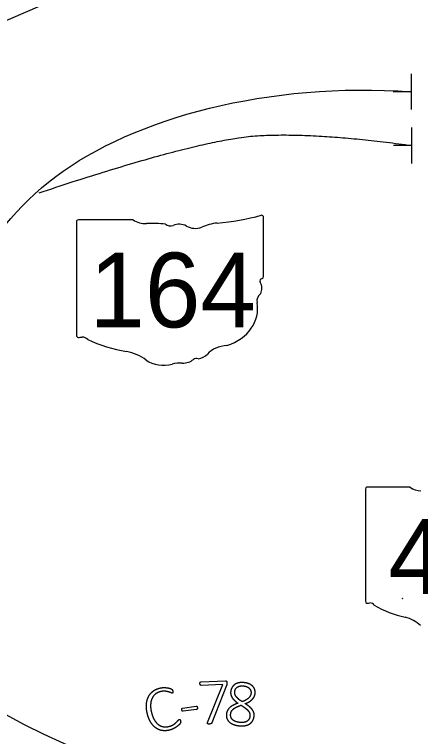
# Model space of a CAD drawing. Extents: x -202 to 1556, y 0 to 676.
# Drawn here: x 150.7 to 191.4, y 37.1 to 109.6 of the extents above; entities that cross this region are included whole.
import ezdxf

# ---------------------------------------------------------------- set-up
doc = ezdxf.new("R2010")
doc.units = 0
for name, color, linetype in [('Default', 7, 'Continuous'), ('GM_X_City_Street', 7, 'Continuous'), ('GM_X_Major_River_Text', 7, 'Continuous'), ('GM_X_Minor_Lake', 7, 'Continuous'), ('GM_X_State_Location', 7, 'Continuous'), ('SH_Data', 7, 'Continuous')]:
    doc.layers.add(name, color=color, linetype=linetype)

msp = doc.modelspace()

# ---------------------------------------------------------------- linework, layer by layer
at = {"layer": 'Default'}
msp.add_open_spline([(153.155, 91.676), (169.005, 96.963), (180.564, 97.806), (190.501, 96.425)], degree=2, dxfattribs=at)
at = {"layer": 'GM_X_City_Street'}
for p, q in [((175.663, 83.279), (175.663, 89.234)), ((156.914, 88.756), (156.914, 77.372)), ((162.589, 88.952), (157.098, 88.952)), ((175.662, 83.28), (175.663, 83.279)), ((185.889, 61.951), (185.889, 50.694)), ((190.378, 62.145), (186.035, 62.145))]:
    msp.add_line(p, q, dxfattribs=at)
for centre, radius, start, end in [((186.059, 61.975), 0.172, 98.1301, 188.1301), ((191.413, 63.451), 1.667, 231.61951, 271.11188), ((186.06, 50.67), 0.173, 171.95839, 258.30661), ((186.087, 51.821), 1.323, 267.33899, 280.60386), ((186.357, 50.045), 0.477, 29.74838, 93.27175), ((192.379, 60.159), 11.358, 240.41292, 257.1985), ((188.993, 45.637), 3.554, 47.18416, 75.83597)]:
    msp.add_arc(centre, radius, start, end, dxfattribs=at)
for centre, major_axis, start_param, end_param in [((168.985, 104.473), (19.884, 0), 4.814394, 5.042369), ((175.456, 89.259), (0.209, 0), 6.141152, 7.989035), ((157.129, 88.78), (0.217, 0), 1.712693, 3.28349), ((163.897, 90.274), (2.107, 0), 4.042523, 4.731795), ((164.596, 82.561), (7.564, 0), 1.404758, 1.657858), ((166.313, 88.839), (0.608, 0), 3.836095, 5.185415), ((167.205, 87.524), (1.264, 0), 0.950623, 2.079405), ((171.521, 85.475), (4, 0), 1.699011, 2.107814), ((168.836, 89.328), (1.52, 0), 4.081561, 5.145723), ((175.615, 82.842), (0.323, 0), 1.883978, 3.671073), ((173.56, 82.089), (1.939, 0), 5.934695, 6.695948), ((175.441, 83.256), (0.223, 0), 5.05454, 6.418171), ((176.411, 80.787), (1.411, 0), 2.387724, 3.262537), ((170.098, 80.029), (4.973, 0), 5.101752, 6.440018), ((157.131, 77.347), (0.219, 0), 3.00124, 4.508301), ((157.164, 78.511), (1.672, 0), 4.665946, 4.897461), ((157.506, 76.715), (0.603, 0), 0.519207, 1.627899), ((165.119, 86.943), (14.359, 0), 4.195997, 4.488961), ((172.195, 74.175), (2.724, 0), 1.647645, 2.488434), ((160.838, 72.257), (4.493, 0), 0.823519, 1.323587), ((168.744, 76.268), (1.607, 0), 4.937069, 5.64225), ((165.697, 76.658), (2.851, 0), 4.026481, 4.996735), ((167.553, 75.806), (1.519, 0), 4.691044, 5.507374), ((168.927, 74.703), (0.428, 0), 1.147584, 2.315152), ((167.344, 72.722), (2.342, 0), 1.495662, 1.94098)]:
    msp.add_ellipse(centre, major_axis=major_axis, ratio=0.8, start_param=start_param, end_param=end_param, dxfattribs=at)
at = {"layer": 'GM_X_Major_River_Text'}
for p, q in [((189.583, 50.986), (189.575, 50.972)), ((189.589, 50.971), (189.589, 50.971)), ((189.595, 50.977), (189.597, 50.977)), ((189.597, 50.975), (189.595, 50.975)), ((189.6, 50.976), (189.6, 50.976)), ((189.605, 50.971), (189.605, 50.971))]:
    msp.add_line(p, q, dxfattribs=at)
for points in [[(189.575, 50.97), (189.584, 50.97), (189.584, 50.965)], [(189.589, 50.972), (189.586, 50.972), (189.586, 50.986)], [(189.586, 50.965), (189.586, 50.97), (189.589, 50.97)]]:
    msp.add_lwpolyline(points, dxfattribs=at)
msp.add_lwpolyline([(189.584, 50.984), (189.584, 50.972), (189.576, 50.972), (189.584, 50.984)], close=True, dxfattribs=at)
for points in [[(189.575, 50.972), (189.574, 50.972), (189.574, 50.972)], [(189.574, 50.972), (189.574, 50.972), (189.574, 50.971)], [(189.574, 50.971), (189.574, 50.971), (189.574, 50.971)], [(189.574, 50.971), (189.574, 50.971), (189.574, 50.971)], [(189.574, 50.971), (189.574, 50.971), (189.574, 50.97)], [(189.574, 50.97), (189.574, 50.97), (189.574, 50.97)], [(189.574, 50.97), (189.574, 50.97), (189.575, 50.97)], [(189.575, 50.97), (189.575, 50.97), (189.575, 50.97)], [(189.584, 50.986), (189.583, 50.986), (189.583, 50.986)], [(189.583, 50.986), (189.583, 50.986), (189.583, 50.986)], [(189.583, 50.986), (189.583, 50.986), (189.583, 50.986)], [(189.585, 50.986), (189.585, 50.986), (189.584, 50.986)], [(189.584, 50.986), (189.584, 50.986), (189.584, 50.986)], [(189.584, 50.965), (189.584, 50.965), (189.584, 50.965)], [(189.584, 50.965), (189.584, 50.965), (189.584, 50.965)], [(189.584, 50.965), (189.584, 50.965), (189.584, 50.965)], [(189.584, 50.965), (189.585, 50.965), (189.585, 50.965)], [(189.586, 50.986), (189.586, 50.986), (189.585, 50.986)], [(189.585, 50.986), (189.585, 50.986), (189.585, 50.986)], [(189.585, 50.965), (189.585, 50.965), (189.585, 50.965)], [(189.585, 50.965), (189.586, 50.965), (189.586, 50.965)], [(189.586, 50.986), (189.586, 50.986), (189.586, 50.986)], [(189.586, 50.965), (189.586, 50.965), (189.586, 50.965)], [(189.586, 50.965), (189.586, 50.965), (189.586, 50.965)], [(189.589, 50.971), (189.589, 50.972), (189.589, 50.972)], [(189.589, 50.971), (189.589, 50.971), (189.589, 50.971)], [(189.589, 50.97), (189.589, 50.97), (189.589, 50.971)], [(189.589, 50.97), (189.589, 50.97), (189.589, 50.97)], [(189.592, 50.967), (189.592, 50.968), (189.592, 50.968)], [(189.592, 50.968), (189.592, 50.968), (189.593, 50.968)], [(189.592, 50.966), (189.592, 50.967), (189.592, 50.967)], [(189.592, 50.967), (189.592, 50.967), (189.592, 50.967)], [(189.593, 50.966), (189.593, 50.966), (189.592, 50.966)], [(189.592, 50.966), (189.592, 50.966), (189.592, 50.966)], [(189.592, 50.966), (189.592, 50.966), (189.592, 50.966)], [(189.593, 50.984), (189.593, 50.984), (189.593, 50.985)], [(189.593, 50.985), (189.593, 50.985), (189.594, 50.985)], [(189.593, 50.983), (189.593, 50.983), (189.593, 50.984)], [(189.593, 50.984), (189.593, 50.984), (189.593, 50.984)], [(189.593, 50.984), (189.593, 50.984), (189.593, 50.984)], [(189.593, 50.984), (189.593, 50.984), (189.593, 50.984)], [(189.594, 50.983), (189.593, 50.983), (189.593, 50.983)], [(189.593, 50.983), (189.593, 50.983), (189.593, 50.983)], [(189.593, 50.983), (189.593, 50.983), (189.593, 50.983)], [(189.593, 50.983), (189.593, 50.983), (189.593, 50.983)], [(189.593, 50.968), (189.593, 50.968), (189.593, 50.968)], [(189.593, 50.968), (189.594, 50.968), (189.594, 50.967)], [(189.594, 50.965), (189.594, 50.965), (189.593, 50.966)], [(189.594, 50.985), (189.594, 50.985), (189.595, 50.986)], [(189.595, 50.984), (189.594, 50.983), (189.594, 50.983)], [(189.594, 50.975), (189.594, 50.975), (189.594, 50.976)], [(189.594, 50.976), (189.594, 50.976), (189.594, 50.976)], [(189.594, 50.976), (189.594, 50.976), (189.595, 50.976)], [(189.595, 50.975), (189.594, 50.975), (189.594, 50.975)], [(189.594, 50.967), (189.595, 50.967), (189.596, 50.967)], [(189.596, 50.965), (189.595, 50.965), (189.594, 50.965)], [(189.595, 50.986), (189.596, 50.986), (189.596, 50.986)], [(189.596, 50.984), (189.595, 50.984), (189.595, 50.984)], [(189.595, 50.976), (189.595, 50.976), (189.595, 50.977)], [(189.595, 50.977), (189.595, 50.977), (189.595, 50.977)], [(189.595, 50.975), (189.595, 50.975), (189.595, 50.975)], [(189.595, 50.975), (189.595, 50.975), (189.595, 50.975)], [(189.596, 50.986), (189.597, 50.986), (189.598, 50.986)], [(189.598, 50.985), (189.597, 50.985), (189.596, 50.984)], [(189.596, 50.967), (189.597, 50.966), (189.598, 50.966)], [(189.598, 50.965), (189.597, 50.965), (189.596, 50.965)], [(189.597, 50.977), (189.598, 50.977), (189.599, 50.977)], [(189.599, 50.975), (189.598, 50.975), (189.597, 50.975)], [(189.598, 50.986), (189.6, 50.986), (189.601, 50.986)], [(189.6, 50.984), (189.599, 50.985), (189.598, 50.985)], [(189.598, 50.966), (189.599, 50.966), (189.6, 50.967)], [(189.601, 50.965), (189.6, 50.965), (189.598, 50.965)], [(189.599, 50.977), (189.6, 50.977), (189.6, 50.978)], [(189.601, 50.974), (189.601, 50.974), (189.599, 50.975)], [(189.601, 50.984), (189.6, 50.984), (189.6, 50.984)], [(189.6, 50.978), (189.601, 50.978), (189.602, 50.979)], [(189.602, 50.977), (189.601, 50.976), (189.6, 50.976)], [(189.6, 50.976), (189.601, 50.976), (189.602, 50.975)], [(189.6, 50.967), (189.601, 50.967), (189.602, 50.967)], [(189.601, 50.986), (189.602, 50.986), (189.603, 50.985)], [(189.602, 50.982), (189.601, 50.983), (189.601, 50.984)], [(189.602, 50.972), (189.602, 50.973), (189.601, 50.974)], [(189.603, 50.966), (189.602, 50.965), (189.601, 50.965)], [(189.602, 50.981), (189.602, 50.982), (189.602, 50.982)], [(189.602, 50.979), (189.602, 50.98), (189.602, 50.981)], [(189.603, 50.978), (189.602, 50.977), (189.602, 50.977)], [(189.602, 50.975), (189.603, 50.975), (189.603, 50.974)], [(189.603, 50.971), (189.603, 50.971), (189.602, 50.972)], [(189.602, 50.969), (189.603, 50.97), (189.603, 50.971)], [(189.602, 50.967), (189.602, 50.968), (189.602, 50.969)], [(189.603, 50.985), (189.603, 50.984), (189.604, 50.983)], [(189.604, 50.979), (189.603, 50.978), (189.603, 50.978)], [(189.603, 50.974), (189.604, 50.974), (189.605, 50.973)], [(189.604, 50.968), (189.604, 50.967), (189.603, 50.966)], [(189.604, 50.983), (189.604, 50.982), (189.604, 50.981)], [(189.604, 50.981), (189.604, 50.98), (189.604, 50.979)], [(189.605, 50.971), (189.605, 50.969), (189.604, 50.968)], [(189.605, 50.973), (189.605, 50.972), (189.605, 50.971)]]:
    msp.add_open_spline(points, degree=2, dxfattribs=at)
at = {"layer": 'GM_X_Minor_Lake'}
for p, q in [((190.455, 103.624), (190.478, 100.024)), ((190.467, 101.824), (188.667, 101.813)), ((190.49, 98.224), (190.513, 94.625)), ((190.501, 96.425), (188.702, 96.413))]:
    msp.add_line(p, q, dxfattribs=at)
at = {"layer": 'GM_X_State_Location'}
for p, q in [((169.4, 42.603), (171.841, 42.69)), ((171.95, 42.232), (170.483, 38.502)), ((171.998, 42.519), (171.998, 42.519)), ((174.406, 41.437), (174.406, 41.437)), ((167.548, 39.973), (168.91, 40.159)), ((169.027, 40.01), (169.027, 40.01)), ((168.955, 39.834), (167.593, 39.648)), ((174.298, 39.138), (174.298, 39.138)), ((174.722, 39.148), (174.722, 39.148)), ((167.339, 38.676), (167.339, 38.676))]:
    msp.add_line(p, q, dxfattribs=at)
msp.add_lwpolyline([(170.056, 38.509), (171.585, 42.324), (169.413, 42.246)], dxfattribs=at)
for points in [[(169.286, 42.421), (169.284, 42.464), (169.291, 42.497)], [(169.321, 42.295), (169.288, 42.346), (169.286, 42.421)], [(169.291, 42.497), (169.298, 42.53), (169.314, 42.554)], [(169.314, 42.554), (169.329, 42.577), (169.35, 42.589)], [(169.413, 42.246), (169.354, 42.243), (169.321, 42.295)], [(169.35, 42.589), (169.371, 42.602), (169.4, 42.603)], [(171.841, 42.69), (171.884, 42.692), (171.914, 42.683)], [(171.914, 42.683), (171.943, 42.674), (171.961, 42.652)], [(171.975, 42.306), (171.965, 42.272), (171.95, 42.232)], [(171.961, 42.652), (171.978, 42.63), (171.987, 42.597)], [(171.99, 42.376), (171.985, 42.341), (171.975, 42.306)], [(171.987, 42.597), (171.997, 42.565), (171.998, 42.519)], [(171.998, 42.445), (171.996, 42.411), (171.99, 42.376)], [(171.998, 42.519), (172, 42.48), (171.998, 42.445)], [(172.757, 42.32), (172.587, 42.196), (172.491, 42.019)], [(173.173, 42.499), (172.926, 42.444), (172.757, 42.32)], [(172.783, 41.618), (172.819, 41.927), (173.047, 42.08)], [(173.047, 42.08), (173.274, 42.233), (173.669, 42.188)], [(173.744, 42.518), (173.421, 42.555), (173.173, 42.499)], [(173.669, 42.188), (173.862, 42.166), (174.008, 42.103)], [(174.261, 42.38), (174.047, 42.483), (173.744, 42.518)], [(174.008, 42.103), (174.155, 42.04), (174.249, 41.941)], [(174.607, 42.131), (174.475, 42.278), (174.261, 42.38)], [(174.79, 41.803), (174.739, 41.984), (174.607, 42.131)], [(164.105, 41.071), (164.265, 41.407), (164.549, 41.637)], [(164.794, 41.357), (164.582, 41.18), (164.466, 40.911)], [(164.549, 41.637), (164.834, 41.867), (165.225, 41.966)], [(165.295, 41.608), (165.006, 41.535), (164.794, 41.357)], [(165.225, 41.966), (165.409, 42.013), (165.591, 42.022)], [(165.766, 41.658), (165.559, 41.675), (165.295, 41.608)], [(165.591, 42.022), (165.773, 42.031), (165.933, 42.014)], [(166.125, 41.596), (165.973, 41.642), (165.766, 41.658)], [(165.933, 42.014), (166.093, 41.997), (166.227, 41.957)], [(166.375, 41.506), (166.277, 41.55), (166.125, 41.596)], [(166.227, 41.957), (166.36, 41.916), (166.414, 41.884)], [(166.517, 41.473), (166.472, 41.461), (166.375, 41.506)], [(166.414, 41.884), (166.468, 41.852), (166.484, 41.836)], [(166.484, 41.836), (166.5, 41.82), (166.512, 41.798)], [(166.512, 41.798), (166.524, 41.775), (166.535, 41.746)], [(166.552, 41.495), (166.539, 41.478), (166.517, 41.473)], [(166.535, 41.746), (166.546, 41.717), (166.556, 41.679)], [(166.57, 41.538), (166.564, 41.512), (166.552, 41.495)], [(166.556, 41.679), (166.567, 41.634), (166.571, 41.6)], [(166.571, 41.6), (166.575, 41.565), (166.57, 41.538)], [(172.371, 41.637), (172.351, 41.464), (172.389, 41.306)], [(172.491, 42.019), (172.394, 41.842), (172.371, 41.637)], [(172.804, 41.352), (172.767, 41.478), (172.783, 41.618)], [(172.931, 41.105), (172.841, 41.226), (172.804, 41.352)], [(174.406, 41.437), (174.374, 41.161), (174.145, 40.955)], [(174.249, 41.941), (174.344, 41.843), (174.383, 41.715)], [(174.383, 41.715), (174.423, 41.587), (174.406, 41.437)], [(174.723, 41.106), (174.8, 41.257), (174.82, 41.433)], [(174.82, 41.433), (174.842, 41.622), (174.79, 41.803)], [(163.92, 40.303), (163.945, 40.734), (164.105, 41.071)], [(164.466, 40.911), (164.351, 40.641), (164.338, 40.286)], [(172.389, 41.306), (172.427, 41.149), (172.52, 41.002)], [(172.52, 41.002), (172.614, 40.856), (172.762, 40.721)], [(172.762, 40.721), (172.91, 40.585), (173.109, 40.456)], [(173.167, 40.863), (173.021, 40.984), (172.931, 41.105)], [(173.52, 40.61), (173.314, 40.743), (173.167, 40.863)], [(174.145, 40.955), (173.916, 40.749), (173.52, 40.61)], [(173.821, 40.41), (174.042, 40.494), (174.217, 40.597)], [(174.217, 40.597), (174.392, 40.701), (174.519, 40.828)], [(174.519, 40.828), (174.646, 40.955), (174.723, 41.106)], [(164.021, 39.369), (163.894, 39.872), (163.92, 40.303)], [(164.338, 40.286), (164.325, 39.931), (164.434, 39.502)], [(167.473, 39.797), (167.46, 39.888), (167.483, 39.927)], [(167.483, 39.927), (167.506, 39.967), (167.548, 39.973)], [(168.91, 40.159), (168.93, 40.162), (168.949, 40.156)], [(168.949, 40.156), (168.968, 40.15), (168.983, 40.133)], [(169.018, 39.878), (168.997, 39.84), (168.955, 39.834)], [(168.983, 40.133), (168.999, 40.115), (169.01, 40.085)], [(169.01, 40.085), (169.021, 40.055), (169.027, 40.01)], [(169.027, 40.01), (169.04, 39.915), (169.018, 39.878)], [(172.3, 40.041), (172.152, 39.913), (172.06, 39.75)], [(172.654, 40.269), (172.449, 40.169), (172.3, 40.041)], [(172.458, 39.661), (172.53, 39.784), (172.658, 39.888)], [(173.109, 40.456), (172.858, 40.37), (172.654, 40.269)], [(172.658, 39.888), (172.785, 39.992), (172.974, 40.081)], [(172.974, 40.081), (173.162, 40.17), (173.41, 40.256)], [(173.41, 40.256), (173.647, 40.107), (173.823, 39.976)], [(174.237, 40.116), (174.058, 40.261), (173.821, 40.41)], [(173.823, 39.976), (174, 39.845), (174.112, 39.715)], [(174.532, 39.818), (174.417, 39.972), (174.237, 40.116)], [(164.362, 38.529), (164.146, 38.88), (164.021, 39.369)], [(164.434, 39.502), (164.538, 39.092), (164.707, 38.797)], [(167.518, 39.674), (167.485, 39.706), (167.473, 39.797)], [(167.593, 39.648), (167.55, 39.642), (167.518, 39.674)], [(171.945, 39.379), (171.916, 39.132), (171.991, 38.93)], [(172.06, 39.75), (171.969, 39.588), (171.945, 39.379)], [(172.551, 38.807), (172.328, 39.029), (172.368, 39.378)], [(172.368, 39.378), (172.386, 39.537), (172.458, 39.661)], [(174.298, 39.138), (174.259, 38.807), (173.994, 38.641)], [(174.112, 39.715), (174.224, 39.585), (174.27, 39.445)], [(174.27, 39.445), (174.317, 39.304), (174.298, 39.138)], [(174.695, 39.501), (174.646, 39.665), (174.532, 39.818)], [(174.571, 38.685), (174.691, 38.881), (174.722, 39.148)], [(174.722, 39.148), (174.743, 39.337), (174.695, 39.501)], [(164.865, 37.973), (164.578, 38.177), (164.362, 38.529)], [(164.707, 38.797), (164.877, 38.502), (165.101, 38.327)], [(166.626, 38.308), (166.802, 38.422), (166.918, 38.536)], [(166.918, 38.536), (167.035, 38.65), (167.105, 38.737)], [(167.105, 38.737), (167.176, 38.824), (167.224, 38.837)], [(167.32, 38.453), (167.297, 38.415), (167.213, 38.321)], [(167.224, 38.837), (167.243, 38.841), (167.258, 38.837)], [(167.258, 38.837), (167.272, 38.832), (167.286, 38.813)], [(167.286, 38.813), (167.299, 38.795), (167.312, 38.761)], [(167.312, 38.761), (167.326, 38.727), (167.339, 38.676)], [(167.348, 38.513), (167.342, 38.491), (167.32, 38.453)], [(167.339, 38.676), (167.348, 38.641), (167.352, 38.612)], [(167.355, 38.559), (167.355, 38.535), (167.348, 38.513)], [(167.352, 38.612), (167.356, 38.582), (167.355, 38.559)], [(170.05, 38.401), (170.033, 38.42), (170.037, 38.446)], [(170.037, 38.446), (170.041, 38.473), (170.056, 38.509)], [(170.449, 38.436), (170.43, 38.411), (170.401, 38.397)], [(170.483, 38.502), (170.468, 38.462), (170.449, 38.436)], [(171.991, 38.93), (172.065, 38.728), (172.227, 38.578)], [(172.227, 38.578), (172.39, 38.427), (172.633, 38.331)], [(173.26, 38.53), (172.775, 38.586), (172.551, 38.807)], [(173.994, 38.641), (173.729, 38.475), (173.26, 38.53)], [(174.254, 38.369), (174.451, 38.489), (174.571, 38.685)], [(165.501, 37.713), (165.152, 37.768), (164.865, 37.973)], [(165.101, 38.327), (165.324, 38.152), (165.601, 38.1)], [(166.237, 37.756), (165.849, 37.658), (165.501, 37.713)], [(165.601, 38.1), (165.878, 38.049), (166.193, 38.129)], [(166.193, 38.129), (166.45, 38.194), (166.626, 38.308)], [(166.666, 37.916), (166.478, 37.817), (166.237, 37.756)], [(166.991, 38.121), (166.854, 38.015), (166.666, 37.916)], [(167.213, 38.321), (167.129, 38.227), (166.991, 38.121)], [(170.108, 38.373), (170.067, 38.382), (170.05, 38.401)], [(170.225, 38.368), (170.15, 38.365), (170.108, 38.373)], [(170.33, 38.376), (170.287, 38.37), (170.225, 38.368)], [(170.401, 38.397), (170.372, 38.383), (170.33, 38.376)], [(172.633, 38.331), (172.876, 38.235), (173.186, 38.2)], [(173.186, 38.2), (173.518, 38.161), (173.787, 38.205)], [(173.787, 38.205), (174.056, 38.248), (174.254, 38.369)]]:
    msp.add_open_spline(points, degree=2, dxfattribs=at)
at = {"layer": 'SH_Data'}
msp.add_circle((192.681, 118.45), 90, dxfattribs=at)
for points in [[(72.676, 92.438), (98.675, 92.219), (111.174, 94.546), (130.998, 99.432), (168.349, 118.148), (182.667, 118.561)], [(99.584, 38.494), (114.011, 45.821), (142.225, 70.89), (149.271, 95.631), (176.178, 102.836), (190.467, 101.824)]]:
    msp.add_open_spline(points, degree=3, dxfattribs=at)

# ---------------------------------------------------------------- texts
at = {"layer": 'GM_X_City_Street'}
for s, p in [('164', (158.183, 78.174)), ('43', (188.189, 51.428))]:
    msp.add_text(s, height=7.5, dxfattribs=at).set_placement(p)

doc.saveas('drawing.dxf')
